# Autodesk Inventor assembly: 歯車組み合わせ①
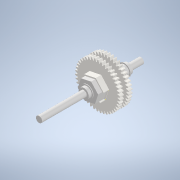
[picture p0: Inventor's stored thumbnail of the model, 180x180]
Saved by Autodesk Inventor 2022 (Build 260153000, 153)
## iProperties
Created: 2024-12
Part Number: 歯車組み合わせ①
Document SubType Name: Assembly
Designer: jsat7
Author: jsat7
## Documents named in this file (7)
- C:\Users\jsat7\OneDrive\デスクトップ\CAD 長田\歯車組み合わせ①.iam
- C:\Users\jsat7\OneDrive\デスクトップ\CAD 長田\六角シャフト.ipt
- C:\Users\jsat7\OneDrive\デスクトップ\CAD 長田\2段平ギア.iam
- C:\Users\jsat7\OneDrive\デスクトップ\CAD 長田\特殊平ギア.ipt
- C:\Users\jsat7\OneDrive\デスクトップ\CAD 長田\固定器具.ipt
- C:\Users\jsat7\OneDrive\デスクトップ\CAD 長田\B3.ipt
- C:\Users\jsat7\OneDrive\デスクトップ\CAD 長田\B7.ipt
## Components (6 placed, 6 different names)
1. 六角シャフト:1 — メイト:1, メイト:2, メイト:3, メイト:5, メイト:6, 円柱状:1
2. 2段平ギア:1 [sub-assembly] — メイト:2
3. 平歯車1:1 — メイト:1, メイト:7
4. 固定器具:1 — メイト:3, メイト:7, 円柱状:1
5. B3:1 — メイト:6
6. B7:1 — メイト:5
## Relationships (7: Mate 6, CylindricalJoint 1)
- メイト:1 [Mate]: 六角シャフト:1 ↔ 平歯車1:1
- メイト:2 [Mate]: 六角シャフト:1 ↔ 2段平ギア:1
- メイト:3 [Mate]: 六角シャフト:1 ↔ 固定器具:1
- メイト:5 [Mate]: 六角シャフト:1 ↔ B7:1
- メイト:6 [Mate]: 六角シャフト:1 ↔ B3:1
- メイト:7 [Mate]: 平歯車1:1 ↔ 固定器具:1
- 円柱状:1 [CylindricalJoint]: 六角シャフト:1 ↔ 固定器具:1
